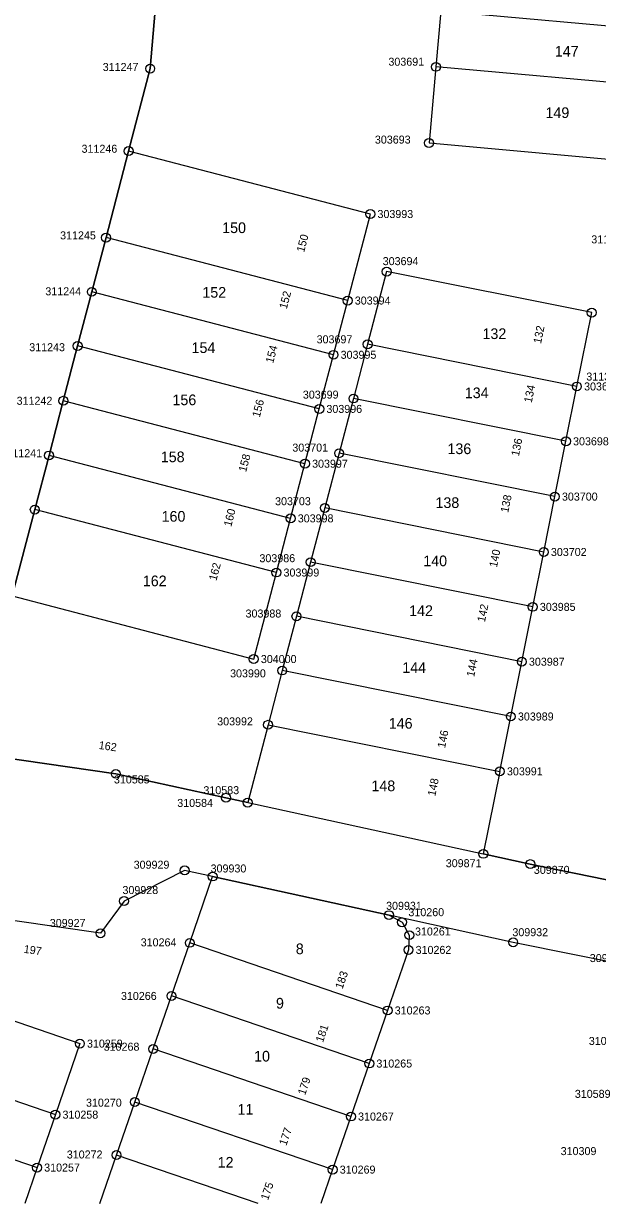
# Model space of a CAD drawing. Extents: x 141995 to 152570, y 6580184 to 6586000.
# Drawn here: x 142089.4 to 142153.9, y 6585000 to 6585132.7 of the extents above; entities that cross this region are included whole.
import ezdxf

# ---------------------------------------------------------------- set-up
doc = ezdxf.new("R2010")
doc.units = 0
for name, color, linetype in [('Level 10', 7, 'Continuous'), ('Level 5', 7, 'Continuous'), ('Level 51', 7, 'Continuous'), ('Level 53', 7, 'Continuous'), ('Level 54', 7, 'Continuous'), ('Level 55', 7, 'Continuous'), ('Level 6', 7, 'Continuous'), ('Level 7', 7, 'Continuous')]:
    doc.layers.add(name, color=color, linetype=linetype)

msp = doc.modelspace()

# ---------------------------------------------------------------- linework, layer by layer
at = {"layer": 'Level 10'}
for centre in [(142103.67, 6585127.62), (142135.79, 6585127.82), (142135.02, 6585119.26), (142101.24, 6585118.35), (142128.42, 6585111.27), (142098.7, 6585108.62), (142130.25, 6585104.79), (142097.1, 6585102.52), (142125.87, 6585101.53), (142153.31, 6585100.18), (142095.51, 6585096.43), (142128.11, 6585096.62), (142124.28, 6585095.44), (142151.64, 6585091.88), (142093.9, 6585090.27), (142126.52, 6585090.52), (142122.68, 6585089.35), (142150.41, 6585085.71), (142124.91, 6585084.37), (142092.29, 6585084.12), (142121.07, 6585083.19), (142149.16, 6585079.49), (142090.69, 6585078.03), (142123.3, 6585078.22), (142119.46, 6585077.04), (142147.92, 6585073.26), (142121.7, 6585072.12), (142117.86, 6585070.95), (142120.11, 6585066.03), (142146.68, 6585067.09), (142115.31, 6585061.22), (142145.45, 6585060.92), (142118.51, 6585059.93), (142116.92, 6585053.83), (142144.21, 6585054.76), (142142.98, 6585048.59), (142099.8, 6585048.31), (142112.19, 6585045.62), (142114.63, 6585045.08), (142141.12, 6585039.31), (142146.4, 6585038.16), (142107.54, 6585037.45), (142110.69, 6585036.76), (142100.73, 6585034.01), (142130.52, 6585032.42), (142131.98, 6585031.62), (142098.08, 6585030.38), (142132.8, 6585030.17), (142108.12, 6585029.3), (142144.48, 6585029.36), (142132.71, 6585028.51), (142106.06, 6585023.33), (142130.36, 6585021.7), (142095.76, 6585017.97), (142104, 6585017.37), (142128.3, 6585015.73), (142101.94, 6585011.4), (142093.01, 6585009.98), (142126.24, 6585009.77), (142099.88, 6585005.44), (142090.95, 6585004.02), (142124.18, 6585003.8)]:
    msp.add_circle(centre, 0.5, dxfattribs=at)
at = {"layer": 'Level 5'}
for points in [[(142103.67, 6585127.62), (142104.72, 6585139.93)], [(142101.24, 6585118.35), (142103.67, 6585127.62)], [(142098.7, 6585108.62), (142101.24, 6585118.35)], [(142097.1, 6585102.52), (142098.7, 6585108.62)], [(142095.51, 6585096.43), (142097.1, 6585102.52)], [(142093.9, 6585090.27), (142095.51, 6585096.43)], [(142092.29, 6585084.12), (142093.9, 6585090.27)], [(142090.69, 6585078.03), (142092.29, 6585084.12)], [(142088.16, 6585068.34), (142090.69, 6585078.03)], [(142099.8, 6585048.31), (142084, 6585050.59)], [(142112.19, 6585045.62), (142099.8, 6585048.31)], [(142114.63, 6585045.08), (142112.19, 6585045.62)], [(142114.63, 6585045.08), (142141.12, 6585039.31)], [(142146.4, 6585038.16), (142141.12, 6585039.31)], [(142107.54, 6585037.45), (142100.73, 6585034.01)], [(142110.69, 6585036.76), (142107.54, 6585037.45)], [(142159.95, 6585035.39), (142146.4, 6585038.16)], [(142110.69, 6585036.76), (142130.52, 6585032.42)], [(142098.08, 6585030.38), (142078.78, 6585033.15)], [(142100.73, 6585034.01), (142098.08, 6585030.38)], [(142144.48, 6585029.36), (142130.52, 6585032.42)], [(142158.27, 6585026.55), (142144.48, 6585029.36)]]:
    msp.add_lwpolyline(points, dxfattribs=at)
at = {"layer": 'Level 6'}
for points in [[(142178.21, 6585198.29), (142167.49, 6585198.75), (142142.24, 6585199.84), (142107.95, 6585201.31), (142107.36, 6585188.37), (142106.97, 6585179.83), (142106.69, 6585173.54), (142106.4, 6585167.24), (142106.11, 6585160.95), (142105.82, 6585154.66), (142105.65, 6585150.82), (142105.44, 6585148.37), (142104.72, 6585139.93), (142103.67, 6585127.62), (142101.24, 6585118.35), (142098.7, 6585108.62), (142097.1, 6585102.52), (142095.51, 6585096.43), (142093.9, 6585090.27), (142092.29, 6585084.12), (142090.69, 6585078.03), (142088.16, 6585068.34)], [(142084, 6585050.59), (142099.8, 6585048.31), (142112.19, 6585045.62), (142114.63, 6585045.08), (142141.12, 6585039.31), (142146.4, 6585038.16), (142159.95, 6585035.39), (142162.17, 6585035), (142173.58, 6585033), (142187.26, 6585030.99), (142190.76, 6585030.58), (142201, 6585029.37), (142202.67, 6585029.22)], [(142266.53, 6585015.16), (142243.89, 6585016.87), (142214.09, 6585019.15), (142212.85, 6585019.26), (142200.07, 6585020.41), (142193.7, 6585021.17), (142186.08, 6585022.06), (142182.71, 6585022.56), (142172.14, 6585024.11), (142160.42, 6585026.17), (142158.27, 6585026.55), (142144.48, 6585029.36), (142130.52, 6585032.42), (142110.69, 6585036.76), (142107.54, 6585037.45), (142100.73, 6585034.01), (142098.08, 6585030.38), (142078.78, 6585033.15), (142075.89, 6585024.79), (142073.13, 6585016.81), (142071.07, 6585010.85), (142069.02, 6585004.9), (142067.33, 6585000)]]:
    msp.add_lwpolyline(points, dxfattribs=at)
at = {"layer": 'Level 7'}
for points in [[(142136.35, 6585134.09), (142135.79, 6585127.82)], [(142161.49, 6585131.84), (142136.35, 6585134.09)], [(142135.79, 6585127.82), (142135.02, 6585119.26)], [(142160.93, 6585125.56), (142135.79, 6585127.82)], [(142128.42, 6585111.27), (142101.24, 6585118.35)], [(142135.02, 6585119.26), (142160.16, 6585117)], [(142125.87, 6585101.53), (142128.42, 6585111.27)], [(142125.87, 6585101.53), (142098.7, 6585108.62)], [(142130.25, 6585104.79), (142128.11, 6585096.62)], [(142153.31, 6585100.18), (142130.25, 6585104.79)], [(142124.28, 6585095.44), (142097.1, 6585102.52)], [(142124.28, 6585095.44), (142125.87, 6585101.53)], [(142151.64, 6585091.88), (142153.31, 6585100.18)], [(142122.68, 6585089.35), (142095.51, 6585096.43)], [(142128.11, 6585096.62), (142126.52, 6585090.52)], [(142151.64, 6585091.88), (142128.11, 6585096.62)], [(142122.68, 6585089.35), (142124.28, 6585095.44)], [(142150.41, 6585085.71), (142151.64, 6585091.88)], [(142121.07, 6585083.19), (142093.9, 6585090.27)], [(142126.52, 6585090.52), (142124.91, 6585084.37)], [(142150.41, 6585085.71), (142126.52, 6585090.52)], [(142121.07, 6585083.19), (142122.68, 6585089.35)], [(142149.16, 6585079.49), (142150.41, 6585085.71)], [(142119.46, 6585077.04), (142092.29, 6585084.12)], [(142124.91, 6585084.37), (142123.3, 6585078.22)], [(142149.16, 6585079.49), (142124.91, 6585084.37)], [(142119.46, 6585077.04), (142121.07, 6585083.19)], [(142123.3, 6585078.22), (142121.7, 6585072.12)], [(142147.92, 6585073.26), (142123.3, 6585078.22)], [(142147.92, 6585073.26), (142149.16, 6585079.49)], [(142117.86, 6585070.95), (142090.69, 6585078.03)], [(142117.86, 6585070.95), (142119.46, 6585077.04)], [(142146.68, 6585067.09), (142147.92, 6585073.26)], [(142121.7, 6585072.12), (142120.11, 6585066.03)], [(142146.68, 6585067.09), (142121.7, 6585072.12)], [(142115.31, 6585061.22), (142117.86, 6585070.95)], [(142088.16, 6585068.34), (142115.31, 6585061.22)], [(142145.45, 6585060.92), (142146.68, 6585067.09)], [(142120.11, 6585066.03), (142118.51, 6585059.93)], [(142145.45, 6585060.92), (142120.11, 6585066.03)], [(142118.51, 6585059.93), (142116.92, 6585053.83)], [(142144.21, 6585054.76), (142118.51, 6585059.93)], [(142144.21, 6585054.76), (142145.45, 6585060.92)], [(142142.98, 6585048.59), (142144.21, 6585054.76)], [(142116.92, 6585053.83), (142114.63, 6585045.08)], [(142116.92, 6585053.83), (142142.98, 6585048.59)], [(142142.98, 6585048.59), (142141.12, 6585039.31)], [(142108.12, 6585029.3), (142110.69, 6585036.76)], [(142130.52, 6585032.42), (142131.98, 6585031.62)], [(142131.98, 6585031.62), (142132.8, 6585030.17)], [(142106.06, 6585023.33), (142108.12, 6585029.3)], [(142130.36, 6585021.7), (142108.12, 6585029.3)], [(142132.8, 6585030.17), (142132.71, 6585028.51)], [(142132.71, 6585028.51), (142130.36, 6585021.7)], [(142075.89, 6585024.79), (142095.76, 6585017.97)], [(142104, 6585017.37), (142106.06, 6585023.33)], [(142128.3, 6585015.73), (142106.06, 6585023.33)], [(142130.36, 6585021.7), (142128.3, 6585015.73)], [(142095.76, 6585017.97), (142093.01, 6585009.98)], [(142101.94, 6585011.4), (142104, 6585017.37)], [(142126.24, 6585009.77), (142104, 6585017.37)], [(142073.13, 6585016.81), (142093.01, 6585009.98)], [(142128.3, 6585015.73), (142126.24, 6585009.77)], [(142071.07, 6585010.85), (142090.95, 6585004.02)], [(142099.88, 6585005.44), (142101.94, 6585011.4)], [(142124.18, 6585003.8), (142101.94, 6585011.4)], [(142093.01, 6585009.98), (142090.95, 6585004.02)], [(142126.24, 6585009.77), (142124.18, 6585003.8)], [(142098, 6585000), (142099.88, 6585005.44)], [(142115.79, 6585000), (142099.88, 6585005.44)], [(142090.95, 6585004.02), (142089.57, 6585000)], [(142124.18, 6585003.8), (142122.87, 6585000)]]:
    msp.add_lwpolyline(points, dxfattribs=at)

# ---------------------------------------------------------------- texts
at = {"layer": 'Level 51'}
for s, rotation, p in [('147', 0.0526, (142149.16, 6585128.97)), ('149', 0.0526, (142148.11, 6585122.07)), ('150', 0.0526, (142111.76, 6585109.13)), ('152', 0.0526, (142109.53, 6585101.86)), ('132', 0.0526, (142141.03, 6585097.21)), ('154', 0.0526, (142108.32, 6585095.64)), ('134', 0.0526, (142139.04, 6585090.56)), ('156', 0.0526, (142106.17, 6585089.77)), ('136', 0.0526, (142137.09, 6585084.27)), ('158', 0.0526, (142104.86, 6585083.36)), ('138', 0.0526, (142135.74, 6585078.21)), ('160', 0.0526, (142104.95, 6585076.67)), ('140', 0.0526, (142134.37, 6585071.66)), ('162', 0.0526, (142102.84, 6585069.41)), ('142', 0.0522, (142132.78, 6585066.06)), ('144', 0.0522, (142132.01, 6585059.66)), ('146', 0.0522, (142130.49, 6585053.39)), ('148', 0.0522, (142128.54, 6585046.36)), ('8', 0.0522, (142120.04, 6585028.03)), ('9', 0.0522, (142117.81, 6585021.91)), ('10', 0.0522, (142115.35, 6585015.95)), ('11', 0.0522, (142113.49, 6585009.98)), ('12', 0.0522, (142111.25, 6585004.02))]:
    msp.add_text(s, height=1.2, rotation=rotation, dxfattribs=at).set_placement(p)
at = {"layer": 'Level 53'}
for s, rotation, p in [('303691', 0.0526, (142130.45, 6585127.95)), ('311247', 0.0526, (142098.33, 6585127.36)), ('303693', 0.0526, (142128.93, 6585119.19)), ('311246', 0.0526, (142095.95, 6585118.16)), ('303993', 0.0526, (142129.22, 6585110.82)), ('311245', 0.0526, (142093.54, 6585108.42)), ('311328', 0.0526, (142153.26, 6585107.97)), ('303694', 0.0526, (142129.81, 6585105.52)), ('311244', 0.0526, (142091.88, 6585102.13)), ('303994', 0.0526, (142126.67, 6585101.09)), ('303697', 0.0526, (142122.38, 6585096.73)), ('311243', 0.0526, (142090.07, 6585095.84)), ('303995', 0.0526, (142125.08, 6585094.99)), ('311327', 0.0526, (142152.7, 6585092.54)), ('303696', 0.0526, (142152.45, 6585091.43)), ('311242', 0.0526, (142088.65, 6585089.82)), ('303699', 0.0526, (142120.83, 6585090.51)), ('303996', 0.0526, (142123.48, 6585088.9)), ('303698', 0.0526, (142151.21, 6585085.26)), ('303701', 0.0526, (142119.65, 6585084.55)), ('311241', 0.0526, (142087.5, 6585083.92)), ('303997', 0.0526, (142121.87, 6585082.74)), ('303700', 0.0522, (142149.96, 6585079.04)), ('303703', 0.0526, (142117.71, 6585078.52)), ('303998', 0.0526, (142120.26, 6585076.59)), ('303986', 0.0526, (142115.95, 6585072.11)), ('303702', 0.0522, (142148.72, 6585072.81)), ('303999', 0.0526, (142118.66, 6585070.5)), ('303988', 0.0526, (142114.39, 6585065.89)), ('303985', 0.0522, (142147.48, 6585066.64)), ('304000', 0.0526, (142116.11, 6585060.77)), ('303987', 0.0522, (142146.25, 6585060.47)), ('303990', 0.0522, (142112.65, 6585059.16)), ('303992', 0.0522, (142111.2, 6585053.76)), ('303989', 0.0522, (142145.01, 6585054.31)), ('303991', 0.0522, (142143.78, 6585048.14)), ('310585', 0.0522, (142099.59, 6585047.23)), ('310583', 0.0522, (142109.65, 6585046.02)), ('310584', 0.0522, (142106.71, 6585044.59)), ('309929', 0.0522, (142101.81, 6585037.64)), ('309871', 0.0522, (142136.9, 6585037.81)), ('309930', 0.0522, (142110.46, 6585037.22)), ('309870', 0.0522, (142146.8, 6585037.06)), ('309928', 0.0522, (142100.55, 6585034.79)), ('309931', 0.0522, (142130.19, 6585033.02)), ('310260', 0.0522, (142132.7, 6585032.3)), ('309927', 0.0522, (142092.38, 6585031.09)), ('310261', 0.0522, (142133.44, 6585030.13)), ('309932', 0.0522, (142144.39, 6585030.05)), ('310264', 0.0522, (142102.6, 6585028.91)), ('310262', 0.0522, (142133.51, 6585028.06)), ('309933', 0.0522, (142153.09, 6585027.14)), ('310266', 0.0522, (142100.38, 6585022.88)), ('310263', 0.0522, (142131.16, 6585021.25)), ('310591', 0.0522, (142152.98, 6585017.82)), ('310259', 0.0522, (142096.56, 6585017.52)), ('310268', 0.0522, (142098.44, 6585017.17)), ('310265', 0.0522, (142129.1, 6585015.28)), ('310589', 0.0522, (142151.41, 6585011.87)), ('310270', 0.0522, (142096.45, 6585010.88)), ('310258', 0.0522, (142093.81, 6585009.53)), ('310267', 0.0522, (142127.04, 6585009.32)), ('310272', 0.0522, (142094.29, 6585005.05)), ('310309', 0.0522, (142149.82, 6585005.43)), ('310257', 0.0522, (142091.75, 6585003.58)), ('310269', 0.0522, (142124.98, 6585003.35))]:
    msp.add_text(s, height=0.9, rotation=rotation, dxfattribs=at).set_placement(p)
at = {"layer": 'Level 54'}
for s, rotation, p in [('150', 75.3283, (142120.97, 6585106.91)), ('152', 75.3213, (142119.02, 6585100.53)), ('132', 78.6024, (142147.61, 6585096.64)), ('154', 75.3263, (142117.49, 6585094.43)), ('134', 78.6004, (142146.56, 6585089.99)), ('156', 75.3273, (142115.98, 6585088.34)), ('136', 78.6004, (142145.12, 6585083.98)), ('158', 75.3323, (142114.45, 6585082.2)), ('138', 78.6004, (142143.92, 6585077.63)), ('160', 75.3273, (142112.78, 6585076.05)), ('140', 78.6, (142142.65, 6585071.48)), ('162', 75.3273, (142111.11, 6585069.97)), ('142', 78.599, (142141.3, 6585065.33)), ('144', 78.598, (142140.09, 6585059.16)), ('146', 78.599, (142136.82, 6585051.16)), ('148', 78.593, (142135.72, 6585045.75)), ('183', 70.9592, (142125.28, 6585024.04)), ('181', 71.1522, (142123.09, 6585018.04)), ('179', 71.1372, (142121.08, 6585012.11)), ('177', 71.1362, (142118.97, 6585006.43)), ('175', 71.1512, (142116.91, 6585000.29))]:
    msp.add_text(s, height=0.9, rotation=rotation, dxfattribs=at).set_placement(p)
at = {"layer": 'Level 55'}
for s, rotation, p in [('162', 351.8058, (142097.84, 6585051.12)), ('197', 351.826, (142089.41, 6585028.19))]:
    msp.add_text(s, height=0.9, rotation=rotation, dxfattribs=at).set_placement(p)

doc.saveas('drawing.dxf')
